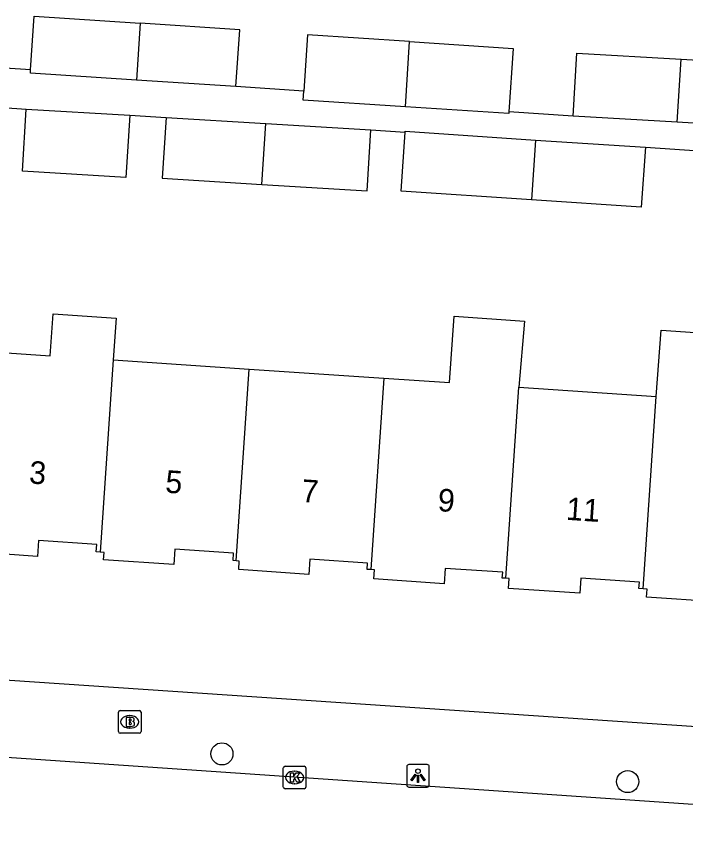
# Model space of a CAD drawing. Extents: x 161848 to 162726, y 385382 to 386521.
# Drawn here: x 162135.49 to 162165.09, y 386221.96 to 386257.98 of the extents above; entities that cross this region are included whole.
import ezdxf

# ---------------------------------------------------------------- set-up
doc = ezdxf.new("R2010")
doc.units = 0
for name, color, linetype in [('IMGEO_Boom', 7, 'Continuous'), ('IMGEO_Brandkraan', 7, 'Continuous'), ('IMGEO_Kolk', 7, 'Continuous'), ('IMGEO_Lichtpunt', 7, 'Continuous'), ('IMGEO_Pand', 7, 'Continuous'), ('IMGEO_Pand_nummerreeks', 7, 'Continuous'), ('IMGEO_Rijbaan_lokaal_open', 7, 'Continuous'), ('IMGEO_Voetpad_open', 7, 'Continuous')]:
    doc.layers.add(name, color=color, linetype=linetype)

msp = doc.modelspace()

# ---------------------------------------------------------------- linework, layer by layer
at = {"layer": 'IMGEO_Boom'}
for centre in [(162144.58, 386225.36), (162162.525, 386224.133)]:
    msp.add_circle(centre, 0.489, dxfattribs=at)
at = {"layer": 'IMGEO_Brandkraan'}
for p, q in [((162140, 386226.348), (162140, 386227.2)), ((162140.075, 386227.274), (162140.927, 386227.274)), ((162141.001, 386227.2), (162141.001, 386226.348)), ((162140.488, 386227.054), (162140.513, 386227.054)), ((162140.511, 386226.494), (162140.486, 386226.494)), ((162140.927, 386226.274), (162140.075, 386226.274))]:
    msp.add_line(p, q, dxfattribs=at)
for points in [[(162140, 386226.348), (162140, 386227.2)], [(162140.075, 386227.274), (162140.927, 386227.274)], [(162141.001, 386227.2), (162141.001, 386226.348)], [(162140.348, 386226.974), (162140.348, 386226.574), (162140.561, 386226.574)], [(162140.579, 386226.974), (162140.348, 386226.974)], [(162140.527, 386226.893), (162140.473, 386226.893), (162140.473, 386226.817)], [(162140.473, 386226.817), (162140.526, 386226.817)], [(162140.535, 386226.741), (162140.473, 386226.741), (162140.473, 386226.66)], [(162140.473, 386226.66), (162140.535, 386226.66)], [(162140.927, 386226.274), (162140.075, 386226.274)]]:
    msp.add_lwpolyline(points, dxfattribs=at)
for centre, radius, start, end in [((162140.077, 386227.198), 0.0765, 91.552, 178.448), ((162140.077, 386227.198), 0.0765, 91.552, 178.448), ((162140.925, 386227.198), 0.0765, 1.552, 88.448), ((162140.925, 386227.198), 0.0765, 1.552, 88.448), ((162140.528, 386226.855), 0.0379, 267.8285, 90.9355), ((162140.583, 386226.829), 0.145, 59.4692, 91.5367), ((162140.608, 386226.876), 0.0922, 285.5137, 58.1501), ((162140.536, 386226.7), 0.0404, 269.8759, 90.5077), ((162140.567, 386226.825), 0.251, 268.6676, 293.5347), ((162140.613, 386226.684), 0.105, 301.3115, 78.989), ((162140.077, 386226.35), 0.0765, 181.552, 268.448), ((162140.077, 386226.35), 0.0765, 181.552, 268.448), ((162140.925, 386226.35), 0.0765, 271.552, 358.448), ((162140.925, 386226.35), 0.0765, 271.552, 358.448)]:
    msp.add_arc(centre, radius, start, end, dxfattribs=at)
for centre, major_axis, ratio, start_param, end_param in [((162140.487, 386226.774), (-0.387, 0.002), 0.722429, 4.712389, 7.853982), ((162140.512, 386226.774), (-0.39, 0.002), 0.717154, 1.570796, 4.712389)]:
    msp.add_ellipse(centre, major_axis=major_axis, ratio=ratio, start_param=start_param, end_param=end_param, dxfattribs=at)
at = {"layer": 'IMGEO_Kolk'}
for p, q in [((162147.295, 386223.888), (162147.295, 386224.74)), ((162147.37, 386224.814), (162148.222, 386224.814)), ((162148.296, 386224.74), (162148.296, 386223.888)), ((162147.783, 386224.594), (162147.808, 386224.594)), ((162147.806, 386224.034), (162147.781, 386224.034)), ((162148.222, 386223.814), (162147.37, 386223.814))]:
    msp.add_line(p, q, dxfattribs=at)
for points in [[(162147.295, 386223.888), (162147.295, 386224.74)], [(162147.37, 386224.814), (162148.222, 386224.814)], [(162148.296, 386224.74), (162148.296, 386223.888)], [(162147.616, 386224.514), (162147.739, 386224.514), (162147.739, 386224.363), (162147.869, 386224.514), (162148.033, 386224.514), (162147.887, 386224.363), (162148.04, 386224.114), (162147.888, 386224.114), (162147.803, 386224.278), (162147.739, 386224.211), (162147.739, 386224.114), (162147.616, 386224.114), (162147.616, 386224.514)], [(162148.222, 386223.814), (162147.37, 386223.814)]]:
    msp.add_lwpolyline(points, dxfattribs=at)
for centre, start, end in [((162147.372, 386224.738), 91.552, 178.448), ((162147.372, 386224.738), 91.552, 178.448), ((162148.22, 386224.738), 1.552, 88.448), ((162148.22, 386224.738), 1.552, 88.448), ((162147.372, 386223.89), 181.552, 268.448), ((162147.372, 386223.89), 181.552, 268.448), ((162148.22, 386223.89), 271.552, 358.448), ((162148.22, 386223.89), 271.552, 358.448)]:
    msp.add_arc(centre, 0.0765, start, end, dxfattribs=at)
for centre, major_axis, ratio, start_param, end_param in [((162147.782, 386224.314), (-0.387, 0.002), 0.722429, 4.712389, 7.853982), ((162147.807, 386224.314), (-0.39, 0.002), 0.717154, 1.570796, 4.712389)]:
    msp.add_ellipse(centre, major_axis=major_axis, ratio=ratio, start_param=start_param, end_param=end_param, dxfattribs=at)
at = {"layer": 'IMGEO_Lichtpunt'}
for p, q in [((162152.754, 386224.794), (162152.754, 386223.987)), ((162152.754, 386224.794), (162152.754, 386223.987)), ((162153.656, 386224.889), (162152.848, 386224.889)), ((162153.656, 386224.889), (162152.848, 386224.889)), ((162153.75, 386223.987), (162153.75, 386224.794)), ((162153.75, 386223.987), (162153.75, 386224.794)), ((162152.848, 386223.893), (162153.656, 386223.893)), ((162152.848, 386223.893), (162153.656, 386223.893))]:
    msp.add_line(p, q, dxfattribs=at)
for points in [[(162153.128, 386224.458), (162153.167, 386224.43), (162152.979, 386224.168), (162152.941, 386224.195), (162153.128, 386224.458)], [(162153.23, 386224.41), (162153.277, 386224.41), (162153.277, 386224.088), (162153.23, 386224.088), (162153.23, 386224.41)], [(162153.34, 386224.43), (162153.378, 386224.457), (162153.565, 386224.195), (162153.526, 386224.167), (162153.34, 386224.43)]]:
    msp.add_lwpolyline(points, dxfattribs=at)
msp.add_circle((162153.253, 386224.592), 0.0994, dxfattribs=at)
for centre, start, end in [((162152.848, 386224.794), 90, 180), ((162152.848, 386224.794), 90, 180), ((162153.656, 386224.794), 0, 90), ((162153.656, 386224.794), 0, 90), ((162152.848, 386223.987), 180, 270), ((162152.848, 386223.987), 180, 270), ((162153.656, 386223.987), 270, 0), ((162153.656, 386223.987), 270, 360)]:
    msp.add_arc(centre, 0.0946, start, end, dxfattribs=at)
at = {"layer": 'IMGEO_Pand'}
for points in [[(162136.12, 386255.619), (162136.275, 386257.983), (162140.963, 386257.675)], [(162140.963, 386257.675), (162140.807, 386255.161)], [(162145.201, 386254.873), (162145.366, 386257.386), (162140.963, 386257.675)], [(162152.873, 386256.862), (162148.367, 386257.158), (162148.203, 386254.676)], [(162152.694, 386253.98), (162152.873, 386256.862)], [(162152.873, 386256.862), (162157.457, 386256.562), (162157.273, 386253.755)], [(162160.113, 386253.569), (162160.279, 386256.358), (162164.889, 386256.083)], [(162164.716, 386253.295), (162164.889, 386256.083)], [(162164.889, 386256.083), (162170.65, 386255.741), (162170.484, 386252.952)], [(162140.807, 386255.161), (162136.11, 386255.469), (162136.12, 386255.619)], [(162145.201, 386254.873), (162140.807, 386255.161)], [(162152.694, 386253.98), (162148.177, 386254.277), (162148.203, 386254.676)], [(162140.512, 386253.603), (162140.325, 386250.858), (162135.757, 386251.136), (162135.924, 386253.881)], [(162135.924, 386253.881), (162140.512, 386253.603)], [(162157.273, 386253.755), (162157.268, 386253.68), (162152.694, 386253.98)], [(162142.116, 386253.506), (162141.934, 386250.818), (162146.343, 386250.55)], [(162142.116, 386253.506), (162146.526, 386253.238)], [(162164.716, 386253.295), (162160.113, 386253.569)], [(162146.343, 386250.55), (162146.526, 386253.238)], [(162146.526, 386253.238), (162151.166, 386252.957)], [(162170.484, 386252.952), (162164.716, 386253.295)], [(162146.343, 386250.55), (162151.002, 386250.267), (162151.166, 386252.957)], [(162158.269, 386249.858), (162152.504, 386250.244), (162152.679, 386252.855)], [(162152.679, 386252.855), (162152.682, 386252.897), (162158.449, 386252.511)], [(162158.449, 386252.511), (162158.269, 386249.858)], [(162158.449, 386252.511), (162163.305, 386252.187)], [(162163.305, 386252.187), (162163.125, 386249.534), (162158.269, 386249.858)], [(162133.768, 386243.186), (162136.985, 386242.969), (162137.111, 386244.822), (162139.902, 386244.632), (162139.776, 386242.781)], [(162151.743, 386241.974), (162154.643, 386241.778), (162154.843, 386244.717), (162157.963, 386244.505), (162157.706, 386241.572)], [(162163.78, 386241.162), (162164.011, 386244.094), (162170.014, 386243.686), (162169.769, 386240.759)], [(162139.776, 386242.781), (162139.198, 386234.279)], [(162139.776, 386242.781), (162145.787, 386242.376)], [(162145.21, 386233.898), (162145.787, 386242.376)], [(162145.787, 386242.376), (162151.743, 386241.974)], [(162151.743, 386241.974), (162151.168, 386233.509)], [(162157.132, 386233.124), (162157.706, 386241.572)], [(162157.706, 386241.572), (162163.78, 386241.162)], [(162163.202, 386232.663), (162163.78, 386241.162)], [(162139.198, 386234.279), (162139.024, 386234.291), (162139.046, 386234.62), (162136.469, 386234.794), (162136.422, 386234.095), (162133.337, 386234.303), (162133.362, 386234.671), (162133.19, 386234.683)], [(162145.21, 386233.898), (162145.073, 386233.907), (162145.095, 386234.235), (162142.497, 386234.41), (162142.452, 386233.733), (162139.348, 386233.942), (162139.37, 386234.268), (162139.198, 386234.279)], [(162151.168, 386233.509), (162151.005, 386233.52), (162151.023, 386233.792), (162148.467, 386233.964), (162148.423, 386233.299), (162145.32, 386233.508), (162145.345, 386233.889), (162145.21, 386233.898)], [(162157.132, 386233.124), (162156.979, 386233.134), (162156.996, 386233.391), (162154.446, 386233.563), (162154.401, 386232.885), (162151.303, 386233.094), (162151.33, 386233.498), (162151.168, 386233.509)], [(162163.202, 386232.663), (162163.023, 386232.675), (162163.042, 386232.956), (162160.457, 386233.13), (162160.413, 386232.468), (162157.256, 386232.68), (162157.285, 386233.114), (162157.132, 386233.124)], [(162169.195, 386232.31), (162169.074, 386232.318), (162169.092, 386232.585), (162166.485, 386232.761), (162166.439, 386232.081), (162163.355, 386232.289), (162163.379, 386232.651), (162163.202, 386232.663)]]:
    msp.add_lwpolyline(points, dxfattribs=at)
at = {"layer": 'IMGEO_Rijbaan_lokaal_open'}
msp.add_lwpolyline([(162210.81, 386220.084), (162191.691, 386221.323), (162124.924, 386225.884)], dxfattribs=at)
at = {"layer": 'IMGEO_Voetpad_open'}
for points in [[(162136.12, 386255.619), (162134.994, 386255.693)], [(162148.203, 386254.676), (162145.201, 386254.873)], [(162134.874, 386253.952), (162135.924, 386253.881)], [(162140.512, 386253.603), (162142.116, 386253.506)], [(162160.113, 386253.569), (162157.273, 386253.755)], [(162151.166, 386252.957), (162152.679, 386252.855)], [(162163.305, 386252.187), (162165.683, 386252.027)], [(162126.45, 386229.203), (162211.018, 386223.504)]]:
    msp.add_lwpolyline(points, dxfattribs=at)

# ---------------------------------------------------------------- texts
at = {"layer": 'IMGEO_Pand_nummerreeks'}
for s, rotation, p in [('3', 356.1268, (162136.031, 386237.323)), ('5', 356.1259, (162142.054, 386236.915)), ('7', 356.1259, (162148.078, 386236.508)), ('9', 356.1259, (162154.102, 386236.1)), ('11', 356.1259, (162159.782, 386235.715))]:
    msp.add_text(s, height=1, rotation=rotation, dxfattribs=at).set_placement(p)

doc.saveas('drawing.dxf')
